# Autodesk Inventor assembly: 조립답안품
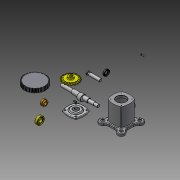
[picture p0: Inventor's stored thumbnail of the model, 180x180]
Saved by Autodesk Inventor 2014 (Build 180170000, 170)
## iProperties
Created: 2016-05
Part Number: 조립답안품
Document SubType Name: Assembly
Designer: Administrator
Author: Administrator
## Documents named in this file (12)
- C:\Users\Administrator\Desktop\460507V1016\조립답안품.iam
- C:\Users\Administrator\Desktop\460507V1016\본체1.ipt
- C:\Users\Administrator\Desktop\460507V1016\M4x0.7x12.ipt
- C:\Users\Administrator\Desktop\460507V1016\베어링-6203.ipt
- C:\Users\Administrator\Desktop\460507V1016\부시.ipt
- C:\Users\Administrator\Desktop\460507V1016\스퍼기어.ipt
- C:\Users\Administrator\Desktop\460507V1016\스프로킷.ipt
- C:\Users\Administrator\Desktop\460507V1016\슬라이더.ipt
- C:\Users\Administrator\Desktop\460507V1016\오일실.ipt
- C:\Users\Administrator\Desktop\460507V1016\커버.ipt
- C:\Users\Administrator\Desktop\460507V1016\키5x5.ipt
- C:\Users\Administrator\Desktop\460507V1016\편심축.ipt
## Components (5 placed, 1 different names)
1. M4x0.7x12:1
2. M4x0.7x12:2
3. M4x0.7x12:3
4. M4x0.7x12:4
5. M4x0.7x12:5
